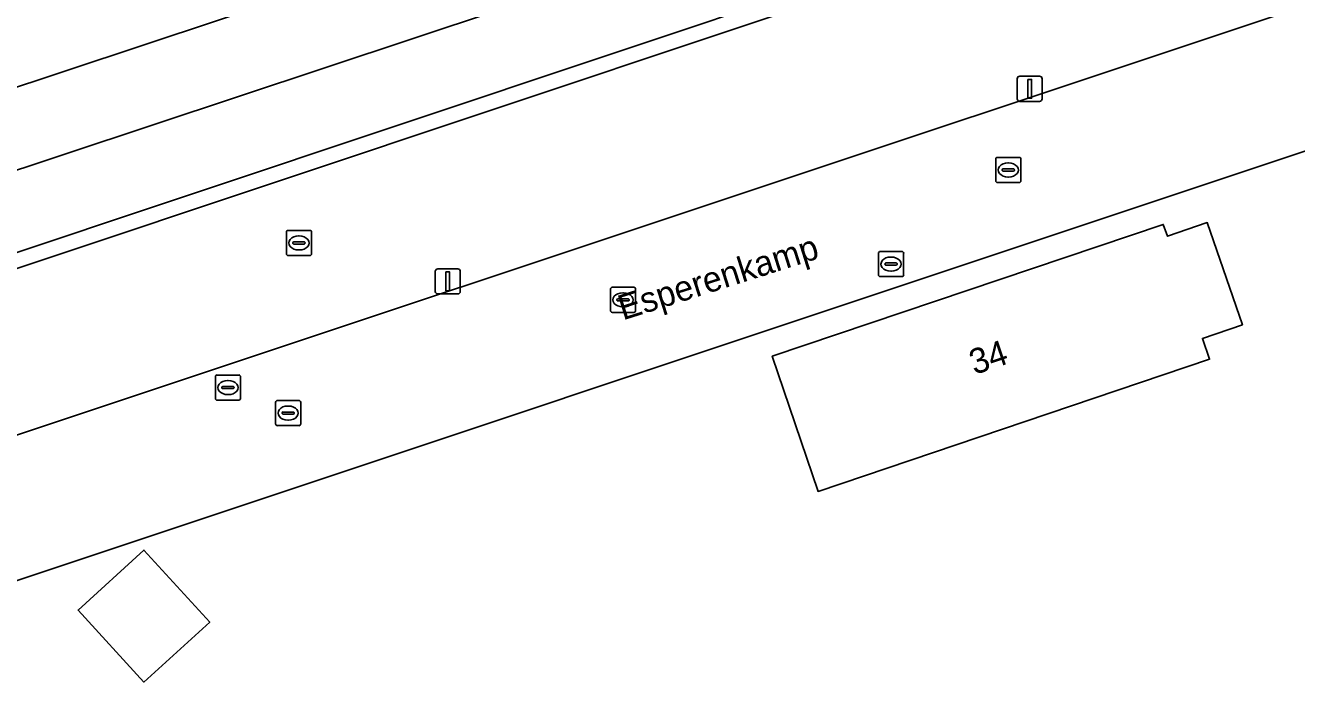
# Model space of a CAD drawing. Extents: x 162082 to 163401, y 388089 to 388636.
# Drawn here: x 162323.5 to 162374, y 388504.2 to 388530.6 of the extents above; entities that cross this region are included whole.
import ezdxf

# ---------------------------------------------------------------- set-up
doc = ezdxf.new("R2010")
doc.units = 0
for name, color, linetype in [('IMGEO_Berm_groen', 7, 'Continuous'), ('IMGEO_Brandkraan', 7, 'Continuous'), ('IMGEO_Erf', 7, 'Continuous'), ('IMGEO_Fietspad_gesloten', 7, 'Continuous'), ('IMGEO_Groenvoorziening', 7, 'Continuous'), ('IMGEO_Kolk', 7, 'Continuous'), ('IMGEO_Lichtmast', 7, 'Continuous'), ('IMGEO_Muur', 7, 'Continuous'), ('IMGEO_Openbare_ruimte_label', 7, 'Continuous'), ('IMGEO_Pand', 7, 'Continuous'), ('IMGEO_Pand_nummerreeks', 7, 'Continuous'), ('IMGEO_Rijbaan_lokaal_open', 7, 'Continuous'), ('IMGEO_Rioolput', 7, 'Continuous'), ('IMGEO_Voetpad_open', 7, 'Continuous')]:
    doc.layers.add(name, color=color, linetype=linetype)

msp = doc.modelspace()

# ---------------------------------------------------------------- linework, layer by layer
at = {"layer": 'IMGEO_Berm_groen'}
msp.add_lwpolyline([(162520.527, 388586.182), (162520.922, 388586.037), (162527.032, 388580.803), (162527.255, 388580.37), (162527.4, 388578.214), (162528.501, 388578.326), (162528.996, 388578.377), (162528.682, 388581.286), (162520.573, 388588.069), (162515.7, 388587.719), (162508.323, 388586.366), (162506.331, 388585.858), (162500, 388583.748), (162408.33, 388553.192), (162359.569, 388536.999), (162273.308, 388508.352), (162273.962, 388506.386), (162287.972, 388511.055), (162288.31, 388509.989), (162413.523, 388551.803)], dxfattribs=at)
at = {"layer": 'IMGEO_Brandkraan'}
for p, q in [((162357.401, 388520.729), (162357.401, 388521.581)), ((162357.476, 388521.655), (162358.328, 388521.655)), ((162357.703, 388521.198), (162358.101, 388521.198)), ((162357.889, 388521.435), (162357.914, 388521.435)), ((162358.402, 388521.581), (162358.402, 388520.729)), ((162357.66, 388521.149), (162357.66, 388521.161)), ((162358.098, 388521.112), (162357.7, 388521.112)), ((162357.912, 388520.875), (162357.887, 388520.875)), ((162358.144, 388521.161), (162358.144, 388521.149)), ((162358.328, 388520.655), (162357.476, 388520.655))]:
    msp.add_line(p, q, dxfattribs=at)
for points in [[(162357.401, 388520.729), (162357.401, 388521.581)], [(162357.476, 388521.655), (162358.328, 388521.655)], [(162358.402, 388521.581), (162358.402, 388520.729)], [(162358.328, 388520.655), (162357.476, 388520.655)]]:
    msp.add_lwpolyline(points, dxfattribs=at)
for centre, radius, start, end in [((162357.478, 388521.579), 0.0765, 91.552, 178.448), ((162357.478, 388521.579), 0.0765, 91.552, 178.448), ((162357.7, 388521.158), 0.0403, 85.8775, 175.7526), ((162358.105, 388521.16), 0.0386, 1.7309, 96.639), ((162358.326, 388521.579), 0.0765, 1.552, 88.448), ((162358.326, 388521.579), 0.0765, 1.552, 88.448), ((162357.478, 388520.731), 0.0765, 181.552, 268.448), ((162357.478, 388520.731), 0.0765, 181.552, 268.448), ((162357.697, 388521.148), 0.0366, 178.938, 274.7102), ((162358.101, 388521.155), 0.043, 264.8664, 352.4533), ((162358.326, 388520.731), 0.0765, 271.552, 358.448), ((162358.326, 388520.731), 0.0765, 271.552, 358.448)]:
    msp.add_arc(centre, radius, start, end, dxfattribs=at)
for centre, major_axis, ratio, start_param, end_param in [((162357.888, 388521.155), (-0.387, 0.002), 0.722429, 4.712389, 7.853982), ((162357.913, 388521.155), (-0.39, 0.002), 0.717154, 1.570796, 4.712389)]:
    msp.add_ellipse(centre, major_axis=major_axis, ratio=ratio, start_param=start_param, end_param=end_param, dxfattribs=at)
at = {"layer": 'IMGEO_Erf'}
msp.add_lwpolyline([(162406.62, 388500.18), (162400.34, 388500.33), (162400.42, 388503.52), (162406.71, 388503.36), (162407.163, 388521.119), (162407.388, 388529.916), (162388.381, 388530.322), (162301.437, 388501.333)], dxfattribs=at)
for points in [[(162370.281, 388518.196), (162370.565, 388517.368), (162355, 388512.113), (162353.18, 388517.493), (162368.725, 388522.735), (162368.887, 388522.264), (162370.475, 388522.808), (162371.869, 388518.741)], [(162328.198, 388504.531), (162325.58, 388507.397), (162328.196, 388509.785), (162330.813, 388506.919)]]:
    msp.add_lwpolyline(points, close=True, dxfattribs=at)
at = {"layer": 'IMGEO_Fietspad_gesloten'}
msp.add_lwpolyline([(162245.441, 388505.444), (162247.114, 388502.698), (162249.604, 388503.789), (162358.353, 388539.891), (162407.328, 388556.149)], dxfattribs=at)
at = {"layer": 'IMGEO_Groenvoorziening'}
msp.add_lwpolyline([(162289.858, 388503.273), (162391.677, 388537.203), (162407.598, 388536.86), (162407.72, 388541.754), (162405.921, 388548.632), (162287.922, 388509.227)], close=True, dxfattribs=at)
at = {"layer": 'IMGEO_Kolk'}
for p, q in [((162362.062, 388524.471), (162362.062, 388525.323)), ((162362.137, 388525.397), (162362.989, 388525.397)), ((162363.063, 388525.323), (162363.063, 388524.471)), ((162362.321, 388524.891), (162362.321, 388524.903)), ((162362.759, 388524.854), (162362.361, 388524.854)), ((162362.364, 388524.94), (162362.762, 388524.94)), ((162362.55, 388525.177), (162362.575, 388525.177)), ((162362.805, 388524.903), (162362.805, 388524.891)), ((162362.989, 388524.397), (162362.137, 388524.397)), ((162362.573, 388524.617), (162362.548, 388524.617)), ((162346.745, 388519.305), (162346.745, 388520.157)), ((162346.82, 388520.231), (162347.672, 388520.231)), ((162347.746, 388520.157), (162347.746, 388519.305)), ((162347.004, 388519.725), (162347.004, 388519.737)), ((162347.442, 388519.688), (162347.044, 388519.688)), ((162347.047, 388519.774), (162347.445, 388519.774)), ((162347.233, 388520.011), (162347.258, 388520.011)), ((162347.488, 388519.737), (162347.488, 388519.725)), ((162347.672, 388519.231), (162346.82, 388519.231)), ((162347.256, 388519.451), (162347.231, 388519.451)), ((162333.431, 388514.804), (162333.431, 388515.656)), ((162333.506, 388515.73), (162334.358, 388515.73)), ((162334.432, 388515.656), (162334.432, 388514.804)), ((162333.69, 388515.224), (162333.69, 388515.236)), ((162334.128, 388515.187), (162333.73, 388515.187)), ((162333.733, 388515.273), (162334.131, 388515.273)), ((162333.919, 388515.51), (162333.944, 388515.51)), ((162334.174, 388515.236), (162334.174, 388515.224)), ((162334.358, 388514.73), (162333.506, 388514.73)), ((162333.942, 388514.95), (162333.917, 388514.95))]:
    msp.add_line(p, q, dxfattribs=at)
for points in [[(162362.062, 388524.471), (162362.062, 388525.323)], [(162362.137, 388525.397), (162362.989, 388525.397)], [(162363.063, 388525.323), (162363.063, 388524.471)], [(162362.989, 388524.397), (162362.137, 388524.397)], [(162346.745, 388519.305), (162346.745, 388520.157)], [(162346.82, 388520.231), (162347.672, 388520.231)], [(162347.746, 388520.157), (162347.746, 388519.305)], [(162347.672, 388519.231), (162346.82, 388519.231)], [(162333.431, 388514.804), (162333.431, 388515.656)], [(162333.506, 388515.73), (162334.358, 388515.73)], [(162334.432, 388515.656), (162334.432, 388514.804)], [(162334.358, 388514.73), (162333.506, 388514.73)]]:
    msp.add_lwpolyline(points, dxfattribs=at)
for centre, radius, start, end in [((162362.139, 388525.321), 0.0765, 91.552, 178.448), ((162362.139, 388525.321), 0.0765, 91.552, 178.448), ((162362.987, 388525.321), 0.0765, 1.552, 88.448), ((162362.987, 388525.321), 0.0765, 1.552, 88.448), ((162362.361, 388524.9), 0.0403, 85.8775, 175.7526), ((162362.358, 388524.89), 0.0366, 178.938, 274.7102), ((162362.762, 388524.897), 0.043, 264.8664, 352.4533), ((162362.766, 388524.902), 0.0386, 1.7309, 96.639), ((162362.139, 388524.473), 0.0765, 181.552, 268.448), ((162362.139, 388524.473), 0.0765, 181.552, 268.448), ((162362.987, 388524.473), 0.0765, 271.552, 358.448), ((162362.987, 388524.473), 0.0765, 271.552, 358.448), ((162346.822, 388520.155), 0.0765, 91.552, 178.448), ((162346.822, 388520.155), 0.0765, 91.552, 178.448), ((162347.67, 388520.155), 0.0765, 1.552, 88.448), ((162347.67, 388520.155), 0.0765, 1.552, 88.448), ((162347.044, 388519.734), 0.0403, 85.8775, 175.7526), ((162347.041, 388519.724), 0.0366, 178.938, 274.7102), ((162347.445, 388519.731), 0.043, 264.8664, 352.4533), ((162347.449, 388519.736), 0.0386, 1.7309, 96.639), ((162346.822, 388519.307), 0.0765, 181.552, 268.448), ((162346.822, 388519.307), 0.0765, 181.552, 268.448), ((162347.67, 388519.307), 0.0765, 271.552, 358.448), ((162347.67, 388519.307), 0.0765, 271.552, 358.448), ((162333.508, 388515.654), 0.0765, 91.552, 178.448), ((162333.508, 388515.654), 0.0765, 91.552, 178.448), ((162334.356, 388515.654), 0.0765, 1.552, 88.448), ((162334.356, 388515.654), 0.0765, 1.552, 88.448), ((162333.73, 388515.233), 0.0403, 85.8775, 175.7526), ((162333.727, 388515.223), 0.0366, 178.938, 274.7102), ((162334.131, 388515.23), 0.043, 264.8664, 352.4533), ((162334.135, 388515.235), 0.0386, 1.7309, 96.639), ((162333.508, 388514.806), 0.0765, 181.552, 268.448), ((162333.508, 388514.806), 0.0765, 181.552, 268.448), ((162334.356, 388514.806), 0.0765, 271.552, 358.448), ((162334.356, 388514.806), 0.0765, 271.552, 358.448)]:
    msp.add_arc(centre, radius, start, end, dxfattribs=at)
for centre, major_axis, ratio, start_param, end_param in [((162362.549, 388524.897), (-0.387, 0.002), 0.722429, 4.712389, 7.853982), ((162362.574, 388524.897), (-0.39, 0.002), 0.717154, 1.570796, 4.712389), ((162347.232, 388519.731), (-0.387, 0.002), 0.722429, 4.712389, 7.853982), ((162347.257, 388519.731), (-0.39, 0.002), 0.717154, 1.570796, 4.712389), ((162333.918, 388515.23), (-0.387, 0.002), 0.722429, 4.712389, 7.853982), ((162333.943, 388515.23), (-0.39, 0.002), 0.717154, 1.570796, 4.712389)]:
    msp.add_ellipse(centre, major_axis=major_axis, ratio=ratio, start_param=start_param, end_param=end_param, dxfattribs=at)
at = {"layer": 'IMGEO_Lichtmast'}
for p, q in [((162362.917, 388527.726), (162362.917, 388528.526)), ((162362.917, 388528.526), (162362.917, 388527.726)), ((162363.017, 388528.626), (162363.807, 388528.626)), ((162363.807, 388528.626), (162363.017, 388528.626)), ((162363.907, 388528.526), (162363.907, 388527.726)), ((162363.907, 388527.726), (162363.907, 388528.526)), ((162363.807, 388527.626), (162363.017, 388527.626)), ((162363.017, 388527.626), (162363.807, 388527.626)), ((162339.782, 388520.067), (162339.782, 388520.867)), ((162339.782, 388520.867), (162339.782, 388520.067)), ((162339.882, 388520.967), (162340.672, 388520.967)), ((162340.672, 388520.967), (162339.882, 388520.967)), ((162340.772, 388520.867), (162340.772, 388520.067)), ((162340.772, 388520.067), (162340.772, 388520.867)), ((162340.672, 388519.967), (162339.882, 388519.967)), ((162339.882, 388519.967), (162340.672, 388519.967))]:
    msp.add_line(p, q, dxfattribs=at)
for points in [[(162363.337, 388528.501), (162363.487, 388528.501), (162363.487, 388527.751), (162363.337, 388527.751), (162363.337, 388528.501)], [(162340.202, 388520.842), (162340.352, 388520.842), (162340.352, 388520.092), (162340.202, 388520.092), (162340.202, 388520.842)]]:
    msp.add_lwpolyline(points, dxfattribs=at)
for centre, start, end in [((162363.017, 388528.526), 90, 180), ((162363.017, 388528.526), 90, 180), ((162363.807, 388528.526), 0, 90), ((162363.807, 388528.526), 360, 90), ((162363.017, 388527.726), 180, 270), ((162363.017, 388527.726), 180, 270), ((162363.807, 388527.726), 270, 0), ((162363.807, 388527.726), 270, 0), ((162339.882, 388520.867), 90, 180), ((162339.882, 388520.867), 90, 180), ((162340.672, 388520.867), 0, 90), ((162340.672, 388520.867), 360, 90), ((162339.882, 388520.067), 180, 270), ((162339.882, 388520.067), 180, 270), ((162340.672, 388520.067), 270, 0), ((162340.672, 388520.067), 270, 0)]:
    msp.add_arc(centre, 0.1, start, end, dxfattribs=at)
at = {"layer": 'IMGEO_Muur'}
msp.add_lwpolyline([(162510.249, 388584.742), (162506.611, 388583.883), (162500, 388581.823), (162413.144, 388552.843), (162413.523, 388551.803), (162288.31, 388509.989), (162287.972, 388511.055), (162273.962, 388506.386), (162274.16, 388505.819), (162287.584, 388510.293), (162287.922, 388509.227), (162405.921, 388548.632)], dxfattribs=at)
at = {"layer": 'IMGEO_Pand'}
for points in [[(162370.475, 388522.808), (162368.887, 388522.264), (162368.725, 388522.735), (162353.18, 388517.493), (162355, 388512.113), (162370.565, 388517.368), (162370.281, 388518.196), (162371.869, 388518.741)], [(162325.58, 388507.397), (162328.198, 388504.531), (162330.813, 388506.919), (162328.196, 388509.785)]]:
    msp.add_lwpolyline(points, close=True, dxfattribs=at)
at = {"layer": 'IMGEO_Rijbaan_lokaal_open'}
msp.add_lwpolyline([(162391.677, 388537.203), (162289.858, 388503.273), (162286.991, 388502.318), (162282.421, 388500.795), (162282.872, 388495.185), (162297.412, 388500), (162301.437, 388501.333), (162388.381, 388530.322), (162407.388, 388529.916), (162410.126, 388527.323), (162411.248, 388527.271), (162411.22, 388528.537), (162417.008, 388533.087), (162419.312, 388533.05), (162419.363, 388534.531), (162419.378, 388534.914), (162413.801, 388535.011)], dxfattribs=at)
at = {"layer": 'IMGEO_Rioolput'}
for p, q in [((162333.86, 388521.569), (162333.86, 388522.421)), ((162333.935, 388522.495), (162334.787, 388522.495)), ((162334.348, 388522.275), (162334.373, 388522.275)), ((162334.861, 388522.421), (162334.861, 388521.569)), ((162334.119, 388521.989), (162334.119, 388522.001)), ((162334.557, 388521.952), (162334.159, 388521.952)), ((162334.162, 388522.038), (162334.56, 388522.038)), ((162334.371, 388521.715), (162334.346, 388521.715)), ((162334.603, 388522.001), (162334.603, 388521.989)), ((162334.787, 388521.495), (162333.935, 388521.495)), ((162331.037, 388515.818), (162331.037, 388516.67)), ((162331.112, 388516.744), (162331.964, 388516.744)), ((162332.038, 388516.67), (162332.038, 388515.818)), ((162331.296, 388516.238), (162331.296, 388516.25)), ((162331.734, 388516.201), (162331.336, 388516.201)), ((162331.339, 388516.287), (162331.737, 388516.287)), ((162331.525, 388516.524), (162331.55, 388516.524)), ((162331.78, 388516.25), (162331.78, 388516.238)), ((162331.964, 388515.744), (162331.112, 388515.744)), ((162331.548, 388515.964), (162331.523, 388515.964))]:
    msp.add_line(p, q, dxfattribs=at)
for points in [[(162333.86, 388521.569), (162333.86, 388522.421)], [(162333.935, 388522.495), (162334.787, 388522.495)], [(162334.861, 388522.421), (162334.861, 388521.569)], [(162334.787, 388521.495), (162333.935, 388521.495)], [(162331.037, 388515.818), (162331.037, 388516.67)], [(162331.112, 388516.744), (162331.964, 388516.744)], [(162332.038, 388516.67), (162332.038, 388515.818)], [(162331.964, 388515.744), (162331.112, 388515.744)]]:
    msp.add_lwpolyline(points, dxfattribs=at)
for centre, radius, start, end in [((162333.937, 388522.419), 0.0765, 91.552, 178.448), ((162333.937, 388522.419), 0.0765, 91.552, 178.448), ((162334.785, 388522.419), 0.0765, 1.552, 88.448), ((162334.785, 388522.419), 0.0765, 1.552, 88.448), ((162334.159, 388521.998), 0.0403, 85.8775, 175.7526), ((162334.156, 388521.988), 0.0366, 178.938, 274.7102), ((162334.56, 388521.995), 0.043, 264.8664, 352.4533), ((162334.564, 388522), 0.0386, 1.7309, 96.639), ((162333.937, 388521.571), 0.0765, 181.552, 268.448), ((162333.937, 388521.571), 0.0765, 181.552, 268.448), ((162334.785, 388521.571), 0.0765, 271.552, 358.448), ((162334.785, 388521.571), 0.0765, 271.552, 358.448), ((162331.114, 388516.668), 0.0765, 91.552, 178.448), ((162331.114, 388516.668), 0.0765, 91.552, 178.448), ((162331.962, 388516.668), 0.0765, 1.552, 88.448), ((162331.962, 388516.668), 0.0765, 1.552, 88.448), ((162331.336, 388516.247), 0.0403, 85.8775, 175.7526), ((162331.333, 388516.237), 0.0366, 178.938, 274.7102), ((162331.737, 388516.244), 0.043, 264.8664, 352.4533), ((162331.741, 388516.249), 0.0386, 1.7309, 96.639), ((162331.114, 388515.82), 0.0765, 181.552, 268.448), ((162331.114, 388515.82), 0.0765, 181.552, 268.448), ((162331.962, 388515.82), 0.0765, 271.552, 358.448), ((162331.962, 388515.82), 0.0765, 271.552, 358.448)]:
    msp.add_arc(centre, radius, start, end, dxfattribs=at)
for centre, major_axis, ratio, start_param, end_param in [((162334.347, 388521.995), (-0.387, 0.002), 0.722429, 4.712389, 7.853982), ((162334.372, 388521.995), (-0.39, 0.002), 0.717154, 1.570796, 4.712389), ((162331.524, 388516.244), (-0.387, 0.002), 0.722429, 4.712389, 7.853982), ((162331.549, 388516.244), (-0.39, 0.002), 0.717154, 1.570796, 4.712389)]:
    msp.add_ellipse(centre, major_axis=major_axis, ratio=ratio, start_param=start_param, end_param=end_param, dxfattribs=at)
at = {"layer": 'IMGEO_Voetpad_open'}
for points in [[(162497.882, 388586.227), (162488.392, 388583.036), (162457.174, 388572.698), (162436.199, 388565.723), (162407.328, 388556.149), (162358.353, 388539.891), (162249.604, 388503.789), (162247.114, 388502.698)], [(162248.431, 388500), (162248.619, 388500.078), (162249.527, 388500.414), (162253.51, 388501.784), (162270.392, 388507.396), (162271.052, 388505.442), (162272.026, 388502.587), (162285.393, 388507.043), (162285.583, 388506.474), (162286.991, 388502.318), (162289.858, 388503.273), (162287.922, 388509.227), (162287.584, 388510.293), (162274.16, 388505.819), (162273.962, 388506.386), (162273.308, 388508.352), (162359.569, 388536.999), (162408.33, 388553.192), (162500, 388583.748)]]:
    msp.add_lwpolyline(points, dxfattribs=at)

# ---------------------------------------------------------------- texts
at = {"layer": 'IMGEO_Openbare_ruimte_label'}
msp.add_text('Esperenkamp', height=1, rotation=17.5831, dxfattribs=at).set_placement((162347.239, 388518.912))
at = {"layer": 'IMGEO_Pand_nummerreeks'}
msp.add_text('34', height=1, rotation=18.6326, dxfattribs=at).set_placement((162361.218, 388516.742))

doc.saveas('drawing.dxf')
